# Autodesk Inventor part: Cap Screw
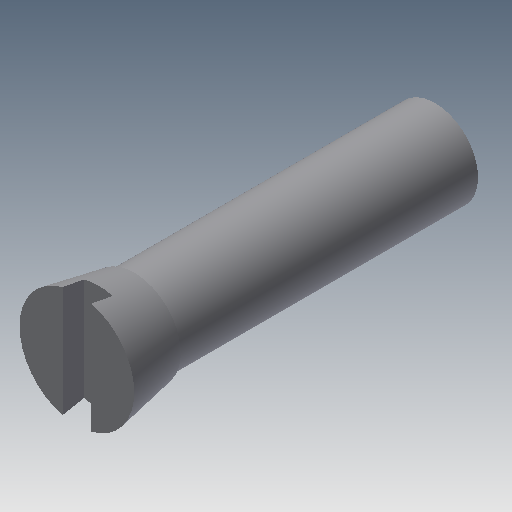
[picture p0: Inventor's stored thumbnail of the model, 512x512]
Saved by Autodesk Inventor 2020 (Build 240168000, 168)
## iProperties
Created: 2002-02
Part Number: Cap Screw
Document SubType Name: Modeling
Designer: ***
Density: 1 g/cm^3
Material: Generic
Mass: 0.736586 g
Surface Area: 5.87035 cm^2
Volume: 0.736586 cm^3
Appearance: Default
Control State: 0
Master: False
Checked Out: False
Shininess: 77.0
Length Units: 11269
Angle Units: 11279
Time Units: 11290
Mass Units: 11283
Length Display Precision: 3
Angle Display Precision: 2
Density: 0.0
Volumn: 0.0
Area: 0.0
PropertySet Name: Model Information
Author: ***
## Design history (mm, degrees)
sketch "Sketch1"
  geometry: L1 (0, 27.83)-(4, 27.83); L2 (4, 27.83)-(3.25, 23.83); L3 (3.25, 23.83)-(0, 23.83); L4 (0, 23.83)-(0, 27.83)
  constraints: 8 end point, 1 horizontal, 1 parallel, 1 perpendicular, 1 point on line
  dimensions: "d2" = 4 distance from line of L1 L2.end; "d5" = 8 diameter of L1.end L4; "d6" = 6.5 diameter of L3.start L4; "d14" = 4 distance of L3.end L1.start
revolve "Revolution1" sketch "Sketch1" stored, may be unused: angle "d7" = 90 deg
sketch "Sketch2"
  geometry: C1 r 3 at (0, 0)
  constraints: 1 centre point
  dimensions: "d8" = 6 diameter of C1
extrude "Extrusion1" join sketch "Sketch2" distance "d9" = 21; taper "d10" = 0 deg
sketch "Sketch3"
  geometry: L1 (-1, 28.967)-(1, 28.967); L2 (1, 28.967)-(1, 26.33); L3 (1, 26.33)-(-1, 26.33); L4 (-1, 26.33)-(-1, 28.967); L5 (-4, 27.83)-(4, 27.83) reference
  constraints: 8 end point, 2 parallel, 1 horizontal, 1 perpendicular
  dimensions: "d11" = 2 distance of L1.start L1.end; "d15" = 1.5 distance between parallel lines of L5 L3
extrude "Extrusion2" cut sketch "Sketch3" extent not by distance; stored distance "d12" = 24; taper "d13" = 0 deg
body "Solid1"
